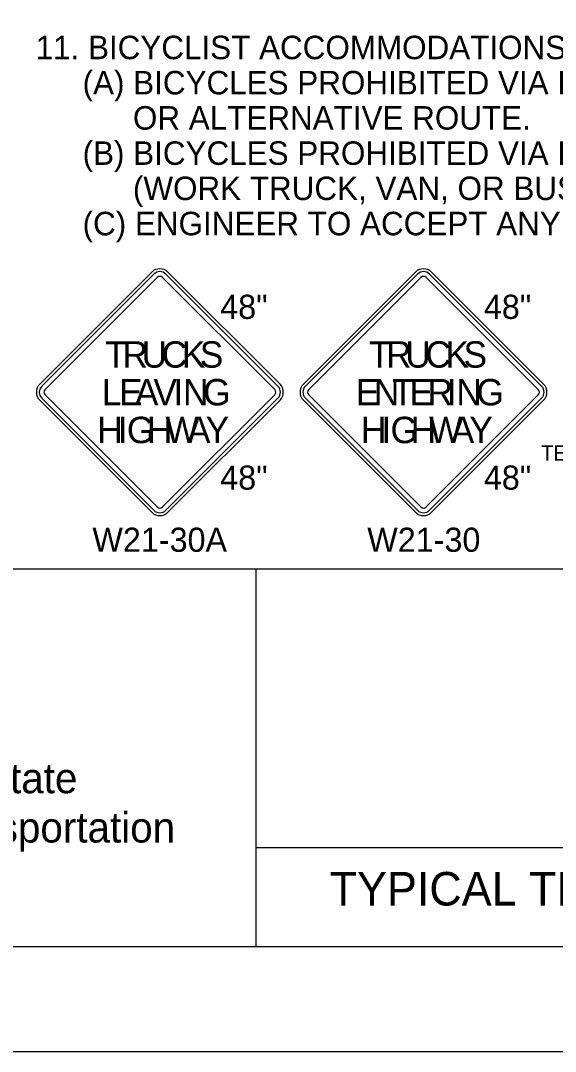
# Model space of a CAD drawing. Extents: x 99999 to 100116, y 99995 to 100013.
# Drawn here: x 100031.504 to 100033.098, y 99999.687 to 100002.761 of the extents above; entities that cross this region are included whole.
import ezdxf

# ---------------------------------------------------------------- set-up
doc = ezdxf.new("R2010")
doc.units = 0
for name, color, linetype in [('SH_GI_GeneralNotesBodyText', 7, 'Continuous'), ('SH_GI_PlotLimits', 7, 'Continuous'), ('SH_GI_SheetBorder', 7, 'Continuous'), ('SH_GI_SheetTextInCells', 7, 'Continuous'), ('SH_GI_TitleBlockText', 7, 'Continuous'), ('TR_SN_ConstructionSigns', 7, 'Continuous')]:
    doc.layers.add(name, color=color, linetype=linetype)

msp = doc.modelspace()

# ---------------------------------------------------------------- linework, layer by layer
at = {"layer": 'SH_GI_PlotLimits'}
msp.add_lwpolyline([(100019.0625, 99999.6875), (100036.0625, 99999.6875), (100036.0625, 100010.6875), (100019.0625, 100010.6875)], close=True, dxfattribs=at)
at = {"layer": 'SH_GI_SheetBorder'}
for p, q in [((100020, 100001.1259), (100035.75, 100001.1259)), ((100032.2055, 100001.1259), (100032.2055, 100000)), ((100032.2055, 100000.2955), (100035.2079, 100000.2955)), ((100020, 100000), (100035.75, 100000))]:
    msp.add_line(p, q, dxfattribs=at)
at = {"layer": 'TR_SN_ConstructionSigns'}
for p, q in [((100031.8955, 100002.0107), (100031.5613, 100001.6766)), ((100031.9014, 100002.0048), (100031.5673, 100001.6707)), ((100031.5773, 100001.6607), (100031.9114, 100001.9948)), ((100031.9273, 100001.9948), (100032.2614, 100001.6607)), ((100032.2713, 100001.6707), (100031.9372, 100002.0048)), ((100032.2773, 100001.6766), (100031.9432, 100002.0107)), ((100032.6812, 100002.0107), (100032.3471, 100001.6766)), ((100032.6871, 100002.0048), (100032.353, 100001.6707)), ((100032.363, 100001.6607), (100032.6971, 100001.9948)), ((100032.713, 100001.9948), (100033.0471, 100001.6607)), ((100033.057, 100001.6707), (100032.7229, 100002.0048)), ((100033.063, 100001.6766), (100032.7289, 100002.0107)), ((100031.5613, 100001.6289), (100031.8955, 100001.2948)), ((100031.5673, 100001.6349), (100031.9014, 100001.3008)), ((100031.9114, 100001.3107), (100031.5773, 100001.6448)), ((100032.2614, 100001.6448), (100031.9273, 100001.3107)), ((100031.9372, 100001.3008), (100032.2713, 100001.6349)), ((100031.9432, 100001.2948), (100032.2773, 100001.6289)), ((100032.3471, 100001.6289), (100032.6812, 100001.2948)), ((100032.353, 100001.6349), (100032.6871, 100001.3008)), ((100032.6971, 100001.3107), (100032.363, 100001.6448)), ((100033.0471, 100001.6448), (100032.713, 100001.3107)), ((100032.7229, 100001.3008), (100033.057, 100001.6349)), ((100032.7289, 100001.2948), (100033.063, 100001.6289))]:
    msp.add_line(p, q, dxfattribs=at)
for centre, radius, start, end in [((100031.9193, 100001.9869), 0.0338, 45, 135), ((100031.9193, 100001.9869), 0.0253, 45, 135), ((100031.9193, 100001.9869), 0.0113, 45, 135), ((100032.705, 100001.9869), 0.0338, 45, 135), ((100032.705, 100001.9869), 0.0253, 45, 135), ((100032.705, 100001.9869), 0.0113, 45, 135), ((100031.5852, 100001.6528), 0.0338, 135, 225), ((100031.5852, 100001.6528), 0.0253, 135, 225), ((100031.5852, 100001.6528), 0.0113, 135, 225), ((100032.2534, 100001.6528), 0.0113, 315, 45), ((100032.2534, 100001.6528), 0.0253, 315, 45), ((100032.2534, 100001.6528), 0.0338, 315, 45), ((100032.3709, 100001.6528), 0.0338, 135, 225), ((100032.3709, 100001.6528), 0.0253, 135, 225), ((100032.3709, 100001.6528), 0.0113, 135, 225), ((100033.0391, 100001.6528), 0.0113, 315, 45), ((100033.0391, 100001.6528), 0.0253, 315, 45), ((100033.0391, 100001.6528), 0.0338, 315, 45), ((100031.9193, 100001.3187), 0.0338, 225, 315), ((100031.9193, 100001.3187), 0.0253, 225, 315), ((100031.9193, 100001.3187), 0.0113, 225, 315), ((100032.705, 100001.3187), 0.0338, 225, 315), ((100032.705, 100001.3187), 0.0253, 225, 315), ((100032.705, 100001.3187), 0.0113, 225, 315)]:
    msp.add_arc(centre, radius, start, end, dxfattribs=at)

# ---------------------------------------------------------------- texts
at = {"layer": 'SH_GI_GeneralNotesBodyText'}
for s, p in [('11. BICYCLIST ACCOMMODATIONS, WHERE FACILITY OPEN TO BICYCLES:', (100031.549, 100002.6456)), ('(A) BICYCLES PROHIBITED VIA R5-601 & R5-6 SIGNS. PROVIDE SIGNED DETOUR ', (100031.689, 100002.5406)), ('OR ALTERNATIVE ROUTE.', (100031.839, 100002.4356)), ('(B) BICYCLES PROHIBITED VIA R5-601 & R5-6 SIGNS. PROVIDE FREE SHUTTLE ', (100031.689, 100002.3306)), ('(WORK TRUCK, VAN, OR BUS OK) + CONTACT INFORMATION OR PHONE BOX.', (100031.839, 100002.2256)), ('(C) ENGINEER TO ACCEPT ANY ALTERNATIVE STRATEGIES.', (100031.689, 100002.1206))]:
    msp.add_text(s, height=0.07, rotation=360, dxfattribs=at).set_placement(p)
at = {"layer": 'SH_GI_SheetTextInCells'}
for s, p in [('Washington State', (100030.7229, 100000.4571)), ('Department of Transportation', (100030.3916, 100000.3101))]:
    msp.add_text(s, height=0.090072, dxfattribs=at).set_placement(p)
at = {"layer": 'SH_GI_TitleBlockText'}
msp.add_text('TYPICAL TRAFFIC CONTROL PLANS', height=0.1, dxfattribs=at).set_placement((100032.4251, 100000.1224))
at = {"layer": 'TR_SN_ConstructionSigns'}
for s, p in [('48"', (100032.0991, 100001.8713)), ('48"', (100032.8848, 100001.8713)), ('48"', (100032.0991, 100001.3622)), ('48"', (100032.8848, 100001.3622)), ('W21-30A', (100031.7182, 100001.1769)), ('W21-30', (100032.5373, 100001.1769))]:
    msp.add_text(s, height=0.072, rotation=360, dxfattribs=at).set_placement(p)
for s, height, p in [('T', 0.0787, (100031.7563, 100001.7259)), ('R', 0.0787, (100031.8075, 100001.7259)), ('U', 0.0787, (100031.865, 100001.7259)), ('C', 0.0787, (100031.9248, 100001.7259)), ('K', 0.0787, (100031.9847, 100001.7259)), ('S', 0.0787, (100032.0382, 100001.7259)), ('T', 0.0787, (100032.542, 100001.7259)), ('R', 0.0787, (100032.5932, 100001.7259)), ('U', 0.0787, (100032.6507, 100001.7259)), ('C', 0.0787, (100032.7106, 100001.7259)), ('K', 0.0787, (100032.7704, 100001.7259)), ('S', 0.0787, (100032.824, 100001.7259)), ('L', 0.0787, (100031.7465, 100001.6134)), ('E', 0.0787, (100031.7977, 100001.6134)), ('A', 0.0787, (100031.8449, 100001.6134)), ('V', 0.0787, (100031.9, 100001.6134)), ('I', 0.0787, (100031.9599, 100001.6134)), ('N', 0.0787, (100031.9882, 100001.6134)), ('G', 0.0787, (100032.0481, 100001.6134)), ('E', 0.0787, (100032.5034, 100001.6134)), ('N', 0.0787, (100032.557, 100001.6134)), ('T', 0.0787, (100032.6121, 100001.6134)), ('E', 0.0787, (100032.6633, 100001.6134)), ('R', 0.0787, (100032.7169, 100001.6134)), ('I', 0.0787, (100032.7743, 100001.6134)), ('N', 0.0787, (100032.8027, 100001.6134)), ('G', 0.0787, (100032.8625, 100001.6134)), ('H', 0.0787, (100031.7327, 100001.5009)), ('I', 0.0787, (100031.7941, 100001.5009)), ('G', 0.0787, (100031.8209, 100001.5009)), ('H', 0.0787, (100031.8807, 100001.5009)), ('W', 0.0787, (100031.9359, 100001.5009)), ('A', 0.0787, (100032.0004, 100001.5009)), ('Y', 0.0787, (100032.0556, 100001.5009)), ('H', 0.0787, (100032.5184, 100001.5009)), ('I', 0.0787, (100032.5798, 100001.5009)), ('G', 0.0787, (100032.6066, 100001.5009)), ('H', 0.0787, (100032.6665, 100001.5009)), ('W', 0.0787, (100032.7216, 100001.5009)), ('A', 0.0787, (100032.7862, 100001.5009)), ('Y', 0.0787, (100032.8413, 100001.5009)), ('TEXT', 0.045, (100033.0554, 100001.4491))]:
    msp.add_text(s, height=height, dxfattribs=at).set_placement(p)

doc.saveas('drawing.dxf')
